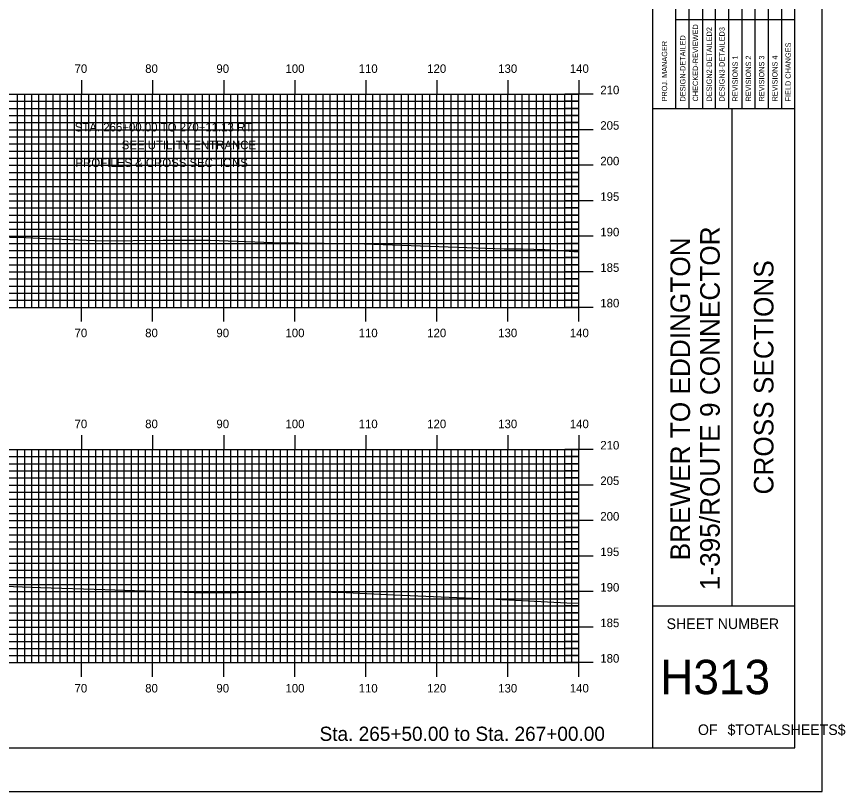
# Model space of a CAD drawing. Extents: x 1807438 to 1807782, y 442591 to 442811.
# Drawn here: x 1807665.1 to 1807781.8, y 442590.5 to 442699.6 of the extents above; entities that cross this region are included whole.
import ezdxf

# ---------------------------------------------------------------- set-up
doc = ezdxf.new("R2010")
doc.units = 0
for name, color, linetype in [('BORDER', 7, 'Continuous'), ('D_Text_Standard', 7, 'Continuous'), ('H_V ANNOTATION', 7, 'Continuous'), ('MAJOR', 7, 'Continuous'), ('MINOR', 7, 'Continuous'), ('PLOT BOUNDARY', 7, 'Continuous'), ('S_Roadway_Centerline', 7, 'Continuous')]:
    doc.layers.add(name, color=color, linetype=linetype)

msp = doc.modelspace()

# ---------------------------------------------------------------- linework, layer by layer
at = {"layer": 'BORDER'}
for p, q in [((1807754.67, 442596.67), (1807754.67, 442806.67)), ((1807754.67, 442686.67), (1807774.67, 442686.67)), ((1807765.85, 442616.67), (1807765.85, 442686.67)), ((1807754.67, 442616.67), (1807774.67, 442616.67))]:
    msp.add_line(p, q, dxfattribs=at)
msp.add_lwpolyline([(1807454.67, 442596.67), (1807774.67, 442596.67), (1807774.67, 442806.67), (1807454.67, 442806.67)], close=True, dxfattribs=at)
for points in [[(1807759.77, 442686.68), (1807759.77, 442721.67)], [(1807761.63, 442721.67), (1807761.63, 442686.68)], [(1807763.49, 442686.68), (1807763.49, 442721.67)], [(1807765.36, 442686.68), (1807765.36, 442721.67)], [(1807767.22, 442686.68), (1807767.22, 442721.67)], [(1807769.08, 442686.68), (1807769.08, 442721.67)], [(1807770.95, 442686.68), (1807770.95, 442721.67)], [(1807772.81, 442686.68), (1807772.81, 442721.67)], [(1807757.9, 442686.68), (1807757.9, 442720.26)], [(1807757.9, 442699.17), (1807774.67, 442699.17)]]:
    msp.add_lwpolyline(points, dxfattribs=at)
at = {"layer": 'MAJOR'}
for p, q in [((1807674.27, 442690.67), (1807674.27, 442688.67)), ((1807684.27, 442690.67), (1807684.27, 442688.67)), ((1807694.27, 442690.67), (1807694.27, 442688.67)), ((1807704.27, 442690.67), (1807704.27, 442688.67)), ((1807714.27, 442690.67), (1807714.27, 442688.67)), ((1807724.27, 442690.67), (1807724.27, 442688.67)), ((1807734.27, 442690.67), (1807734.27, 442688.67)), ((1807744.27, 442690.67), (1807744.27, 442688.67)), ((1807464.27, 442688.67), (1807744.27, 442688.67)), ((1807464.27, 442688.67), (1807744.27, 442688.67)), ((1807674.27, 442658.67), (1807674.27, 442688.67)), ((1807684.27, 442658.67), (1807684.27, 442688.67)), ((1807694.27, 442658.67), (1807694.27, 442688.67)), ((1807704.27, 442658.67), (1807704.27, 442688.67)), ((1807714.27, 442658.67), (1807714.27, 442688.67)), ((1807724.27, 442658.67), (1807724.27, 442688.67)), ((1807734.27, 442658.67), (1807734.27, 442688.67)), ((1807746.28, 442688.67), (1807742.27, 442688.67)), ((1807744.27, 442658.67), (1807744.27, 442688.67)), ((1807744.27, 442658.67), (1807744.27, 442688.67)), ((1807464.27, 442683.67), (1807744.27, 442683.67)), ((1807746.28, 442683.67), (1807742.27, 442683.67)), ((1807464.27, 442678.67), (1807744.27, 442678.67)), ((1807746.28, 442678.67), (1807742.27, 442678.67)), ((1807464.27, 442673.67), (1807744.27, 442673.67)), ((1807746.28, 442673.67), (1807742.27, 442673.67)), ((1807464.27, 442668.67), (1807744.27, 442668.67)), ((1807746.28, 442668.67), (1807742.27, 442668.67)), ((1807464.27, 442663.67), (1807744.27, 442663.67)), ((1807746.28, 442663.67), (1807742.27, 442663.67)), ((1807464.27, 442658.67), (1807744.27, 442658.67)), ((1807464.27, 442658.67), (1807744.27, 442658.67)), ((1807674.27, 442656.66), (1807674.27, 442658.67)), ((1807684.27, 442656.66), (1807684.27, 442658.67)), ((1807694.27, 442656.66), (1807694.27, 442658.67)), ((1807704.27, 442656.66), (1807704.27, 442658.67)), ((1807714.27, 442656.66), (1807714.27, 442658.67)), ((1807724.27, 442656.66), (1807724.27, 442658.67)), ((1807734.27, 442656.66), (1807734.27, 442658.67)), ((1807746.28, 442658.67), (1807742.27, 442658.67)), ((1807744.27, 442656.66), (1807744.27, 442658.67)), ((1807674.27, 442640.67), (1807674.27, 442638.67)), ((1807684.27, 442640.67), (1807684.27, 442638.67)), ((1807694.27, 442640.67), (1807694.27, 442638.67)), ((1807704.27, 442640.67), (1807704.27, 442638.67)), ((1807714.27, 442640.67), (1807714.27, 442638.67)), ((1807724.27, 442640.67), (1807724.27, 442638.67)), ((1807734.27, 442640.67), (1807734.27, 442638.67)), ((1807744.27, 442640.67), (1807744.27, 442638.67)), ((1807464.27, 442638.67), (1807744.27, 442638.67)), ((1807464.27, 442638.67), (1807744.27, 442638.67)), ((1807674.27, 442608.67), (1807674.27, 442638.67)), ((1807684.27, 442608.67), (1807684.27, 442638.67)), ((1807694.27, 442608.67), (1807694.27, 442638.67)), ((1807704.27, 442608.67), (1807704.27, 442638.67)), ((1807714.27, 442608.67), (1807714.27, 442638.67)), ((1807724.27, 442608.67), (1807724.27, 442638.67)), ((1807734.27, 442608.67), (1807734.27, 442638.67)), ((1807746.28, 442638.67), (1807742.27, 442638.67)), ((1807744.27, 442608.67), (1807744.27, 442638.67)), ((1807744.27, 442608.67), (1807744.27, 442638.67)), ((1807464.27, 442633.67), (1807744.27, 442633.67)), ((1807746.28, 442633.67), (1807742.27, 442633.67)), ((1807464.27, 442628.67), (1807744.27, 442628.67)), ((1807746.28, 442628.67), (1807742.27, 442628.67)), ((1807464.27, 442623.67), (1807744.27, 442623.67)), ((1807746.28, 442623.67), (1807742.27, 442623.67)), ((1807464.27, 442618.67), (1807744.27, 442618.67)), ((1807746.28, 442618.67), (1807742.27, 442618.67)), ((1807464.27, 442613.67), (1807744.27, 442613.67)), ((1807746.28, 442613.67), (1807742.27, 442613.67)), ((1807464.27, 442608.67), (1807744.27, 442608.67)), ((1807464.27, 442608.67), (1807744.27, 442608.67)), ((1807674.27, 442606.66), (1807674.27, 442608.67)), ((1807684.27, 442606.66), (1807684.27, 442608.67)), ((1807694.27, 442606.66), (1807694.27, 442608.67)), ((1807704.27, 442606.66), (1807704.27, 442608.67)), ((1807714.27, 442606.66), (1807714.27, 442608.67)), ((1807724.27, 442606.66), (1807724.27, 442608.67)), ((1807734.27, 442606.66), (1807734.27, 442608.67)), ((1807746.28, 442608.67), (1807742.27, 442608.67)), ((1807744.27, 442606.66), (1807744.27, 442608.67))]:
    msp.add_line(p, q, dxfattribs=at)
at = {"layer": 'MINOR'}
for p, q in [((1807665.27, 442658.67), (1807665.27, 442688.67)), ((1807666.27, 442658.67), (1807666.27, 442688.67)), ((1807667.27, 442658.67), (1807667.27, 442688.67)), ((1807668.27, 442658.67), (1807668.27, 442688.67)), ((1807669.27, 442658.67), (1807669.27, 442688.67)), ((1807670.27, 442658.67), (1807670.27, 442688.67)), ((1807671.27, 442658.67), (1807671.27, 442688.67)), ((1807672.27, 442658.67), (1807672.27, 442688.67)), ((1807673.27, 442658.67), (1807673.27, 442688.67)), ((1807675.27, 442658.67), (1807675.27, 442688.67)), ((1807676.27, 442658.67), (1807676.27, 442688.67)), ((1807677.27, 442658.67), (1807677.27, 442688.67)), ((1807678.27, 442658.67), (1807678.27, 442688.67)), ((1807679.27, 442658.67), (1807679.27, 442688.67)), ((1807680.27, 442658.67), (1807680.27, 442688.67)), ((1807681.27, 442658.67), (1807681.27, 442688.67)), ((1807682.27, 442658.67), (1807682.27, 442688.67)), ((1807683.27, 442658.67), (1807683.27, 442688.67)), ((1807685.27, 442658.67), (1807685.27, 442688.67)), ((1807686.27, 442658.67), (1807686.27, 442688.67)), ((1807687.27, 442658.67), (1807687.27, 442688.67)), ((1807688.27, 442658.67), (1807688.27, 442688.67)), ((1807689.27, 442658.67), (1807689.27, 442688.67)), ((1807690.27, 442658.67), (1807690.27, 442688.67)), ((1807691.27, 442658.67), (1807691.27, 442688.67)), ((1807692.27, 442658.67), (1807692.27, 442688.67)), ((1807693.27, 442658.67), (1807693.27, 442688.67)), ((1807695.27, 442658.67), (1807695.27, 442688.67)), ((1807696.27, 442658.67), (1807696.27, 442688.67)), ((1807697.27, 442658.67), (1807697.27, 442688.67)), ((1807698.27, 442658.67), (1807698.27, 442688.67)), ((1807699.27, 442658.67), (1807699.27, 442688.67)), ((1807700.27, 442658.67), (1807700.27, 442688.67)), ((1807701.27, 442658.67), (1807701.27, 442688.67)), ((1807702.27, 442658.67), (1807702.27, 442688.67)), ((1807703.27, 442658.67), (1807703.27, 442688.67)), ((1807705.27, 442658.67), (1807705.27, 442688.67)), ((1807706.27, 442658.67), (1807706.27, 442688.67)), ((1807707.27, 442658.67), (1807707.27, 442688.67)), ((1807708.27, 442658.67), (1807708.27, 442688.67)), ((1807709.27, 442658.67), (1807709.27, 442688.67)), ((1807710.27, 442658.67), (1807710.27, 442688.67)), ((1807711.27, 442658.67), (1807711.27, 442688.67)), ((1807712.27, 442658.67), (1807712.27, 442688.67)), ((1807713.27, 442658.67), (1807713.27, 442688.67)), ((1807715.27, 442658.67), (1807715.27, 442688.67)), ((1807716.27, 442658.67), (1807716.27, 442688.67)), ((1807717.27, 442658.67), (1807717.27, 442688.67)), ((1807718.27, 442658.67), (1807718.27, 442688.67)), ((1807719.27, 442658.67), (1807719.27, 442688.67)), ((1807720.27, 442658.67), (1807720.27, 442688.67)), ((1807721.27, 442658.67), (1807721.27, 442688.67)), ((1807722.27, 442658.67), (1807722.27, 442688.67)), ((1807723.27, 442658.67), (1807723.27, 442688.67)), ((1807725.27, 442658.67), (1807725.27, 442688.67)), ((1807726.27, 442658.67), (1807726.27, 442688.67)), ((1807727.27, 442658.67), (1807727.27, 442688.67)), ((1807728.27, 442658.67), (1807728.27, 442688.67)), ((1807729.27, 442658.67), (1807729.27, 442688.67)), ((1807730.27, 442658.67), (1807730.27, 442688.67)), ((1807731.27, 442658.67), (1807731.27, 442688.67)), ((1807732.27, 442658.67), (1807732.27, 442688.67)), ((1807733.27, 442658.67), (1807733.27, 442688.67)), ((1807735.27, 442658.67), (1807735.27, 442688.67)), ((1807736.27, 442658.67), (1807736.27, 442688.67)), ((1807737.27, 442658.67), (1807737.27, 442688.67)), ((1807738.27, 442658.67), (1807738.27, 442688.67)), ((1807739.27, 442658.67), (1807739.27, 442688.67)), ((1807740.27, 442658.67), (1807740.27, 442688.67)), ((1807741.27, 442658.67), (1807741.27, 442688.67)), ((1807742.27, 442658.67), (1807742.27, 442688.67)), ((1807743.27, 442658.67), (1807743.27, 442688.67)), ((1807464.27, 442687.67), (1807744.27, 442687.67)), ((1807744.27, 442687.67), (1807742.27, 442687.67)), ((1807464.27, 442686.67), (1807744.27, 442686.67)), ((1807744.27, 442686.67), (1807742.27, 442686.67)), ((1807464.27, 442685.67), (1807744.27, 442685.67)), ((1807464.27, 442684.67), (1807744.27, 442684.67)), ((1807744.27, 442685.67), (1807742.27, 442685.67)), ((1807744.27, 442684.67), (1807742.27, 442684.67)), ((1807464.27, 442682.67), (1807744.27, 442682.67)), ((1807744.27, 442682.67), (1807742.27, 442682.67)), ((1807464.27, 442681.67), (1807744.27, 442681.67)), ((1807744.27, 442681.67), (1807742.27, 442681.67)), ((1807464.27, 442680.67), (1807744.27, 442680.67)), ((1807744.27, 442680.67), (1807742.27, 442680.67)), ((1807464.27, 442679.67), (1807744.27, 442679.67)), ((1807744.27, 442679.67), (1807742.27, 442679.67)), ((1807464.27, 442677.67), (1807744.27, 442677.67)), ((1807744.27, 442677.67), (1807742.27, 442677.67)), ((1807464.27, 442676.67), (1807744.27, 442676.67)), ((1807744.27, 442676.67), (1807742.27, 442676.67)), ((1807464.27, 442675.67), (1807744.27, 442675.67)), ((1807744.27, 442675.67), (1807742.27, 442675.67)), ((1807464.27, 442674.67), (1807744.27, 442674.67)), ((1807744.27, 442674.67), (1807742.27, 442674.67)), ((1807464.27, 442672.67), (1807744.27, 442672.67)), ((1807744.27, 442672.67), (1807742.27, 442672.67)), ((1807464.27, 442671.67), (1807744.27, 442671.67)), ((1807464.27, 442670.67), (1807744.27, 442670.67)), ((1807744.27, 442671.67), (1807742.27, 442671.67)), ((1807744.27, 442670.67), (1807742.27, 442670.67)), ((1807464.27, 442669.67), (1807744.27, 442669.67)), ((1807744.27, 442669.67), (1807742.27, 442669.67)), ((1807464.27, 442667.67), (1807744.27, 442667.67)), ((1807744.27, 442667.67), (1807742.27, 442667.67)), ((1807464.27, 442666.67), (1807744.27, 442666.67)), ((1807744.27, 442666.67), (1807742.27, 442666.67)), ((1807464.27, 442665.67), (1807744.27, 442665.67)), ((1807744.27, 442665.67), (1807742.27, 442665.67)), ((1807464.27, 442664.67), (1807744.27, 442664.67)), ((1807744.27, 442664.67), (1807742.27, 442664.67)), ((1807464.27, 442662.67), (1807744.27, 442662.67)), ((1807744.27, 442662.67), (1807742.27, 442662.67)), ((1807464.27, 442661.67), (1807744.27, 442661.67)), ((1807744.27, 442661.67), (1807742.27, 442661.67)), ((1807464.27, 442660.67), (1807744.27, 442660.67)), ((1807744.27, 442660.67), (1807742.27, 442660.67)), ((1807464.27, 442659.67), (1807744.27, 442659.67)), ((1807744.27, 442659.67), (1807742.27, 442659.67)), ((1807665.27, 442608.67), (1807665.27, 442638.67)), ((1807666.27, 442608.67), (1807666.27, 442638.67)), ((1807667.27, 442608.67), (1807667.27, 442638.67)), ((1807668.27, 442608.67), (1807668.27, 442638.67)), ((1807669.27, 442608.67), (1807669.27, 442638.67)), ((1807670.27, 442608.67), (1807670.27, 442638.67)), ((1807671.27, 442608.67), (1807671.27, 442638.67)), ((1807672.27, 442608.67), (1807672.27, 442638.67)), ((1807673.27, 442608.67), (1807673.27, 442638.67)), ((1807675.27, 442608.67), (1807675.27, 442638.67)), ((1807676.27, 442608.67), (1807676.27, 442638.67)), ((1807677.27, 442608.67), (1807677.27, 442638.67)), ((1807678.27, 442608.67), (1807678.27, 442638.67)), ((1807679.27, 442608.67), (1807679.27, 442638.67)), ((1807680.27, 442608.67), (1807680.27, 442638.67)), ((1807681.27, 442608.67), (1807681.27, 442638.67)), ((1807682.27, 442608.67), (1807682.27, 442638.67)), ((1807683.27, 442608.67), (1807683.27, 442638.67)), ((1807685.27, 442608.67), (1807685.27, 442638.67)), ((1807686.27, 442608.67), (1807686.27, 442638.67)), ((1807687.27, 442608.67), (1807687.27, 442638.67)), ((1807688.27, 442608.67), (1807688.27, 442638.67)), ((1807689.27, 442608.67), (1807689.27, 442638.67)), ((1807690.27, 442608.67), (1807690.27, 442638.67)), ((1807691.27, 442608.67), (1807691.27, 442638.67)), ((1807692.27, 442608.67), (1807692.27, 442638.67)), ((1807693.27, 442608.67), (1807693.27, 442638.67)), ((1807695.27, 442608.67), (1807695.27, 442638.67)), ((1807696.27, 442608.67), (1807696.27, 442638.67)), ((1807697.27, 442608.67), (1807697.27, 442638.67)), ((1807698.27, 442608.67), (1807698.27, 442638.67)), ((1807699.27, 442608.67), (1807699.27, 442638.67)), ((1807700.27, 442608.67), (1807700.27, 442638.67)), ((1807701.27, 442608.67), (1807701.27, 442638.67)), ((1807702.27, 442608.67), (1807702.27, 442638.67)), ((1807703.27, 442608.67), (1807703.27, 442638.67)), ((1807705.27, 442608.67), (1807705.27, 442638.67)), ((1807706.27, 442608.67), (1807706.27, 442638.67)), ((1807707.27, 442608.67), (1807707.27, 442638.67)), ((1807708.27, 442608.67), (1807708.27, 442638.67)), ((1807709.27, 442608.67), (1807709.27, 442638.67)), ((1807710.27, 442608.67), (1807710.27, 442638.67)), ((1807711.27, 442608.67), (1807711.27, 442638.67)), ((1807712.27, 442608.67), (1807712.27, 442638.67)), ((1807713.27, 442608.67), (1807713.27, 442638.67)), ((1807715.27, 442608.67), (1807715.27, 442638.67)), ((1807716.27, 442608.67), (1807716.27, 442638.67)), ((1807717.27, 442608.67), (1807717.27, 442638.67)), ((1807718.27, 442608.67), (1807718.27, 442638.67)), ((1807719.27, 442608.67), (1807719.27, 442638.67)), ((1807720.27, 442608.67), (1807720.27, 442638.67)), ((1807721.27, 442608.67), (1807721.27, 442638.67)), ((1807722.27, 442608.67), (1807722.27, 442638.67)), ((1807723.27, 442608.67), (1807723.27, 442638.67)), ((1807725.27, 442608.67), (1807725.27, 442638.67)), ((1807726.27, 442608.67), (1807726.27, 442638.67)), ((1807727.27, 442608.67), (1807727.27, 442638.67)), ((1807728.27, 442608.67), (1807728.27, 442638.67)), ((1807729.27, 442608.67), (1807729.27, 442638.67)), ((1807730.27, 442608.67), (1807730.27, 442638.67)), ((1807731.27, 442608.67), (1807731.27, 442638.67)), ((1807732.27, 442608.67), (1807732.27, 442638.67)), ((1807733.27, 442608.67), (1807733.27, 442638.67)), ((1807735.27, 442608.67), (1807735.27, 442638.67)), ((1807736.27, 442608.67), (1807736.27, 442638.67)), ((1807737.27, 442608.67), (1807737.27, 442638.67)), ((1807738.27, 442608.67), (1807738.27, 442638.67)), ((1807739.27, 442608.67), (1807739.27, 442638.67)), ((1807740.27, 442608.67), (1807740.27, 442638.67)), ((1807741.27, 442608.67), (1807741.27, 442638.67)), ((1807742.27, 442608.67), (1807742.27, 442638.67)), ((1807743.27, 442608.67), (1807743.27, 442638.67)), ((1807464.27, 442637.67), (1807744.27, 442637.67)), ((1807744.27, 442637.67), (1807742.27, 442637.67)), ((1807464.27, 442636.67), (1807744.27, 442636.67)), ((1807464.27, 442635.67), (1807744.27, 442635.67)), ((1807744.27, 442636.67), (1807742.27, 442636.67)), ((1807744.27, 442635.67), (1807742.27, 442635.67)), ((1807464.27, 442634.67), (1807744.27, 442634.67)), ((1807744.27, 442634.67), (1807742.27, 442634.67)), ((1807464.27, 442632.67), (1807744.27, 442632.67)), ((1807744.27, 442632.67), (1807742.27, 442632.67)), ((1807464.27, 442631.67), (1807744.27, 442631.67)), ((1807744.27, 442631.67), (1807742.27, 442631.67)), ((1807464.27, 442630.67), (1807744.27, 442630.67)), ((1807744.27, 442630.67), (1807742.27, 442630.67)), ((1807464.27, 442629.67), (1807744.27, 442629.67)), ((1807744.27, 442629.67), (1807742.27, 442629.67)), ((1807464.27, 442627.67), (1807744.27, 442627.67)), ((1807744.27, 442627.67), (1807742.27, 442627.67)), ((1807464.27, 442626.67), (1807744.27, 442626.67)), ((1807744.27, 442626.67), (1807742.27, 442626.67)), ((1807464.27, 442625.67), (1807744.27, 442625.67)), ((1807744.27, 442625.67), (1807742.27, 442625.67)), ((1807464.27, 442624.67), (1807744.27, 442624.67)), ((1807744.27, 442624.67), (1807742.27, 442624.67)), ((1807464.27, 442622.67), (1807744.27, 442622.67)), ((1807464.27, 442621.67), (1807744.27, 442621.67)), ((1807744.27, 442622.67), (1807742.27, 442622.67)), ((1807744.27, 442621.67), (1807742.27, 442621.67)), ((1807464.27, 442620.67), (1807744.27, 442620.67)), ((1807744.27, 442620.67), (1807742.27, 442620.67)), ((1807464.27, 442619.67), (1807744.27, 442619.67)), ((1807744.27, 442619.67), (1807742.27, 442619.67)), ((1807464.27, 442617.67), (1807744.27, 442617.67)), ((1807744.27, 442617.67), (1807742.27, 442617.67)), ((1807464.27, 442616.67), (1807744.27, 442616.67)), ((1807744.27, 442616.67), (1807742.27, 442616.67)), ((1807464.27, 442615.67), (1807744.27, 442615.67)), ((1807464.27, 442614.67), (1807744.27, 442614.67)), ((1807744.27, 442615.67), (1807742.27, 442615.67)), ((1807744.27, 442614.67), (1807742.27, 442614.67)), ((1807464.27, 442612.67), (1807744.27, 442612.67)), ((1807744.27, 442612.67), (1807742.27, 442612.67)), ((1807464.27, 442611.67), (1807744.27, 442611.67)), ((1807744.27, 442611.67), (1807742.27, 442611.67)), ((1807464.27, 442610.67), (1807744.27, 442610.67)), ((1807744.27, 442610.67), (1807742.27, 442610.67)), ((1807464.27, 442609.67), (1807744.27, 442609.67)), ((1807744.27, 442609.67), (1807742.27, 442609.67))]:
    msp.add_line(p, q, dxfattribs=at)
at = {"layer": 'PLOT BOUNDARY'}
msp.add_lwpolyline([(1807438.49, 442590.55), (1807778.49, 442590.55), (1807778.49, 442810.55), (1807438.49, 442810.55)], close=True, dxfattribs=at)
at = {"layer": 'S_Roadway_Centerline'}
for points in [[(1807648.6, 442668.86), (1807666.43, 442668.5), (1807670.35, 442668.3), (1807677.25, 442668.02), (1807685.73, 442668.13), (1807689.58, 442668.15), (1807692.35, 442668.12), (1807701.17, 442667.81), (1807712.04, 442667.67), (1807712.77, 442667.65), (1807733.76, 442666.91), (1807736.38, 442666.9), (1807739.48, 442666.82), (1807744.27, 442666.48)], [(1807660.85, 442619.54), (1807668.49, 442619.26), (1807677.55, 442618.95), (1807690.12, 442618.52), (1807696.2, 442618.54), (1807702.63, 442618.62), (1807707.43, 442618.62), (1807711.51, 442618.53), (1807718.29, 442618.23), (1807732.58, 442617.6), (1807742.57, 442617.1), (1807744.27, 442617.04)]]:
    msp.add_lwpolyline(points, dxfattribs=at)

# ---------------------------------------------------------------- texts
at = {"layer": 'BORDER'}
for s, height, p in [('CHECKED-REVIEWED', 0.7455, (1807761.03, 442687.65)), ('DESIGN2-DETAILED2', 0.7455, (1807762.97, 442687.65)), ('DESIGN3-DETAILED3', 0.7455, (1807764.76, 442687.65)), ('DESIGN-DETAILED', 0.7455, (1807759.25, 442687.65)), ('PROJ. MANAGER', 0.7455, (1807756.68, 442687.65)), ('FIELD CHANGES', 0.7455, (1807774.08, 442687.65)), ('REVISIONS 1', 0.7455, (1807766.62, 442687.65)), ('REVISIONS 2', 0.7455, (1807768.49, 442687.65)), ('REVISIONS 3', 0.7455, (1807770.35, 442687.65)), ('REVISIONS 4', 0.7455, (1807772.21, 442687.65)), ('1-395/ROUTE 9 CONNECTOR', 2.7557, (1807764.08, 442618.87)), ('BREWER TO EDDINGTON', 2.7557, (1807759.9, 442623.07)), ('CROSS SECTIONS', 2.7557, (1807771.64, 442632.34))]:
    msp.add_text(s, height=height, rotation=90, dxfattribs=at).set_placement(p)
for s, height, p in [('SHEET NUMBER', 1.4905, (1807756.6, 442613.4)), ('H313', 4.839, (1807755.7, 442604.23)), ('OF', 1.491, (1807761.01, 442598.49)), ('$TOTALSHEETS$', 1.4905, (1807765.18, 442598.49))]:
    msp.add_text(s, height=height, dxfattribs=at).set_placement(p)
at = {"layer": 'D_Text_Standard'}
for s, p in [('STA. 266+00.00 TO 270+11.13 RT. ', (1807673.31, 442683.43)), ('SEE UTILITY ENTRANCE', (1807679.92, 442680.93)), ('PROFILES & CROSS SECTIONS', (1807673.41, 442678.43))]:
    msp.add_text(s, height=1.2, dxfattribs=at).set_placement(p)
at = {"layer": 'H_V ANNOTATION'}
for s, height, p in [('70', 1.2, (1807673.28, 442691.67)), ('80', 1.2, (1807683.22, 442691.67)), ('90', 1.2, (1807693.24, 442691.67)), ('100', 1.2, (1807702.96, 442691.67)), ('110', 1.2, (1807713.26, 442691.67)), ('120', 1.2, (1807722.91, 442691.67)), ('130', 1.2, (1807732.9, 442691.67)), ('140', 1.2, (1807742.98, 442691.67)), ('210', 1.2, (1807747.27, 442688.67)), ('205', 1.2, (1807747.27, 442683.67)), ('200', 1.2, (1807747.27, 442678.67)), ('195', 1.2, (1807747.27, 442673.67)), ('190', 1.2, (1807747.27, 442668.67)), ('185', 1.2, (1807747.27, 442663.67)), ('180', 1.2, (1807747.27, 442658.67)), ('70', 1.2, (1807673.28, 442654.47)), ('80', 1.2, (1807683.22, 442654.47)), ('90', 1.2, (1807693.24, 442654.47)), ('100', 1.2, (1807702.96, 442654.47)), ('110', 1.2, (1807713.26, 442654.47)), ('120', 1.2, (1807722.91, 442654.47)), ('130', 1.2, (1807732.9, 442654.47)), ('140', 1.2, (1807742.98, 442654.47)), ('70', 1.2, (1807673.28, 442641.67)), ('80', 1.2, (1807683.22, 442641.67)), ('90', 1.2, (1807693.24, 442641.67)), ('100', 1.2, (1807702.96, 442641.67)), ('110', 1.2, (1807713.26, 442641.67)), ('120', 1.2, (1807722.91, 442641.67)), ('130', 1.2, (1807732.9, 442641.67)), ('140', 1.2, (1807742.98, 442641.67)), ('210', 1.2, (1807747.27, 442638.67)), ('205', 1.2, (1807747.27, 442633.67)), ('200', 1.2, (1807747.27, 442628.67)), ('195', 1.2, (1807747.27, 442623.67)), ('190', 1.2, (1807747.27, 442618.67)), ('185', 1.2, (1807747.27, 442613.67)), ('180', 1.2, (1807747.27, 442608.67)), ('70', 1.2, (1807673.28, 442604.47)), ('80', 1.2, (1807683.22, 442604.47)), ('90', 1.2, (1807693.24, 442604.47)), ('100', 1.2, (1807702.96, 442604.47)), ('110', 1.2, (1807713.26, 442604.47)), ('120', 1.2, (1807722.91, 442604.47)), ('130', 1.2, (1807732.9, 442604.47)), ('140', 1.2, (1807742.98, 442604.47)), ('Sta. 265+50.00 to Sta. 267+00.00', 2.0004, (1807707.76, 442597.66))]:
    msp.add_text(s, height=height, dxfattribs=at).set_placement(p)

doc.saveas('drawing.dxf')
